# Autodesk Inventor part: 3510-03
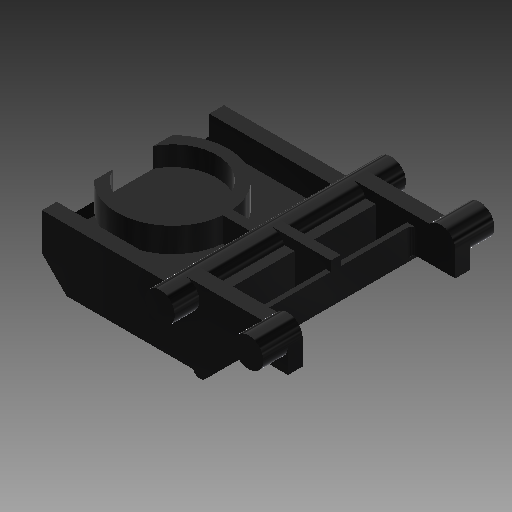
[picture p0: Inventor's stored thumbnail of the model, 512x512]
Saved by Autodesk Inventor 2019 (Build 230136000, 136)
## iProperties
Company: Autodesk Inc.
Created: 2008-12
Part Number: 3510-03
Document SubType Name: Modeling
Designer: Autodesk Inc.
Density: 0.899 g/cm^3
Material: Polypropylene
Mass: 1.31091 g
Surface Area: 20.6383 cm^2
Volume: 1.45818 cm^3
Appearance: Smooth - Black
Description: CARTRIDGE RETAINER
Author: Inventor
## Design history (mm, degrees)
sketch "Sketch1"
  geometry: L1 (-23.967, -12.692)-(-23.967, -6.392); L2 (-3.367, -8.392)-(-3.367, -8.953); L3 (-9.467, -4.892)-(-1.585, -4.892); L4 (1.033, -5.892)-(1.033, -8.392); L5 (-7.387, -12.972)-(-3.367, -8.953); L6 (-23.967, -6.392)-(-10.967, -6.392); L7 (1.033, -8.392)-(-3.367, -8.392); L8 (-8.624, -12.692)-(-23.967, -12.692); A1 r 0.75 centre (-7.917, -12.442) between (-8.624, -12.692) and (-7.387, -12.972); A2 r 1.5 centre (-0.467, -5.892) between (1.033, -5.892) and (-1.585, -4.892); A3 r 1.5 centre (-9.467, -6.392) between (-9.467, -4.892) and (-10.967, -6.392)
  constraints: 16 end point, 6 point on circle, 4 parallel, 3 centre point, 3 tangent, 2 horizontal, 1 equal radius, 1 perpendicular
  dimensions: "d32" = 1.5 radius of A2; "d33" = 0.75 radius of A1; "d34" = 45 deg angle of L4 L5; "d37" = 3.5 distance between parallel lines of L7 L3; "d38" = 4.3 distance between parallel lines of L7 L8; "d39" = 2 distance between parallel lines of L7 L6; "d40" = 2.5 distance from line of L4.start L7; "d132" = 16.05 distance from line of A1.centre L1; "d133" = 15.34289 distance of L8.start L1.start; "d134" = 14.5 distance from line of A3.centre L1; "d135" = 20.6 distance between parallel lines of L2 L1; "d136" = 4.4 distance between parallel lines of L2 L4
extrude "Extrusion1" new body sketch "Sketch1" stored distance "d44" = 18.5; taper "d45" = 0 deg
sketch "Sketch2"
  geometry: L1 (0, 0)-(0, 18.5) reference; L2 (0, 18.5)-(-15.343, 18.5) reference; L3 (0, 17.2)-(-18.782, 17.2); L4 (-18.782, 17.2)-(-18.782, 1.3); L5 (-18.782, 1.3)-(0, 1.3); L6 (0, 1.3)-(0, 17.2); 1 further point
  constraints: 8 end point, 2 parallel, 1 horizontal, 1 perpendicular, 1 point on line
  dimensions: "d49" = 1.3 distance between parallel lines of L3 L2; "d50" = 15.9 distance of L5.end L3.start
extrude "Extrusion2" cut sketch "Sketch2" distance "d51" = 2.36; taper "d52" = 0 deg
sketch "Sketch3"
  geometry: L1 (0, 17.2)-(-15.343, 17.2) reference; L2 (0, 1.3)-(-2.5, 1.3); L3 (-2.5, 1.3)-(-2.5, 17.2); L4 (-2.5, 17.2)-(0, 17.2); L5 (0, 17.2)-(0, 1.3); 1 further point
  constraints: 8 end point, 2 parallel, 1 horizontal, 1 perpendicular, 1 point on line
  dimensions: "d53" = 2.5 distance of L3.end L4.end
extrude "Extrusion3" cut sketch "Sketch3" distance "d54" = 2; taper "d55" = 0 deg
sketch "Sketch4"
  geometry: C1 r 1.5 at (-0.467, -5.892); C2 r 1.5 at (-9.467, -6.392); A1 r 1.5 centre (-0.467, -5.892) between (1.033, -5.892) and (-1.585, -4.892) reference; A2 r 1.5 centre (-9.467, -6.392) between (-9.467, -4.892) and (-10.967, -6.392) reference
  constraints: 2 centre point, 2 coincident, 1 concentric
  dimensions: "d56" = 3 diameter of C2
extrude "Extrusion4" join sketch "Sketch4" distance "d57" = 2.5; taper "d58" = 0 deg
sketch "Sketch5"
  geometry: C1 r 1.5 at (9.467, -6.392); C2 r 1.5 at (0.467, -5.892); A1 r 1.5 centre (9.467, -6.392) between (10.967, -6.392) and (9.467, -4.892) reference; A2 r 1.5 centre (0.467, -5.892) between (1.585, -4.892) and (-1.033, -5.892) reference
  constraints: 2 centre point, 2 coincident, 2 concentric
extrude "Extrusion5" join sketch "Sketch5" distance "d59" = 2.5; taper "d60" = 0 deg
sketch "Sketch6"
  geometry: L1 (0, -18.5)-(0, 0) reference; L2 (0, -18.5)-(4.4, -18.5) reference; L3 (0, -17)-(5.955, -17); L4 (5.955, -17)-(5.955, -1.5); L5 (5.955, -1.5)-(0, -1.5); L6 (0, -1.5)-(0, -17)
  constraints: 8 end point, 2 parallel, 1 horizontal, 1 perpendicular, 1 point on line
  dimensions: "d61" = 1.5 distance between parallel lines of L2 L3; "d62" = 15.5 distance of L3.end L4.end
extrude "Extrusion6" cut sketch "Sketch6" extent not by distance; stored distance "d63" = 2.5; taper "d64" = 0 deg
fillet "Fillet1" dims "d65" = 0.5
fillet "Fillet2" dims "d66" = 0.25
sketch "Sketch7"
  geometry: L1 (0, 0)-(13, 0) reference; L2 (0, 0)-(0, 18.5) reference; L3 (0, 1.5)-(11.5, 1.5); L4 (11.5, 1.5)-(11.5, 17); L5 (11.5, 17)-(0, 17); L6 (0, 17)-(0, 1.5)
  constraints: 8 end point, 2 parallel, 1 horizontal, 1 perpendicular, 1 point on line
  dimensions: "d67" = 1.5 distance between parallel lines of L1 L3; "d68" = 15.5 distance of L3.end L4.end; "d71" = 11.5 distance of L3.start L3.end
extrude "Extrusion7" cut sketch "Sketch7" distance "d69" = 2.5; taper "d70" = 0 deg
chamfer "Chamfer2" distance "d72" = 1; stored, may be unused: second distance "d73" = 2, angle "d74" = 45 deg
sketch "Sketch8"
  geometry: L1 (0, 1.5)-(0, 17) reference; L2 (0, 1.5)-(11.5, 1.5) reference; A1 r 5.65 centre (4, 9.25) between (0, 5.26) and (0, 13.24)
  constraints: 2 point on circle, 2 point on line, 1 centre point
  dimensions: "d75" = 11.3 diameter of A1; "d76" = 4 distance from line of L1 A1.centre; "d77" = 7.75 distance from line of L2 A1.centre
extrude "Extrusion8" join sketch "Sketch8" stored distance "d78" = 2.5; taper "d79" = 0 deg
sketch "Sketch9"
  geometry: C1 r 4.5 at (0, 0); A1 r 5.65 centre (0, 0) between (-4, -3.99) and (-4, 3.99) reference
  constraints: 1 centre point, 1 coincident
  dimensions: "d80" = 9 diameter of C1
extrude "Extrusion9" cut sketch "Sketch9" distance "d81" = 2; taper "d82" = 0 deg
sketch "Sketch10"
  geometry: L1 (11.5, 0)-(0, 0) reference; L2 (12.5, 2.5)-(11.5, 1.5) reference; L3 (0, 0)-(0, 2.5) reference; L4 (0, 0.5)-(0.5, 0)
  constraints: 2 end point, 2 point on line, 1 perpendicular
  dimensions: "d83" = 0.5 distance from line of L1 L4.start
extrude "Extrusion10" join sketch "Sketch10" stored distance "d84" = 2; taper "d85" = 0 deg
sketch "Sketch11"
  geometry: L1 (11.5, 2.5)-(11.5, 0) reference; L2 (11.5, 0)-(0, 0) reference; L3 (11.5, 0.636)-(10.864, 0)
  constraints: 2 end point, 2 point on line
  dimensions: "d86" = 0.63568 distance from line of L2 L3.start; "d87" = 45 deg angle of L2 L3
extrude "Extrusion11" join sketch "Sketch11" stored distance "d88" = 2; taper "d89" = 0 deg
sketch "Sketch12"
  geometry: L1 (12.5, 1.5)-(0, 1.5) reference; L2 (13, 18.5)-(13, 0) reference; L3 (13, 18.5)-(0, 18.5) reference; L4 (0, 17)-(12.5, 17) reference; L5 (12.5, 1.5)-(12.5, 17) reference; L6 (9.65, 9.25)-(12.67, 9.25); L7 (7, 1.5)-(7, 4.462); L8 (7, 14.038)-(7, 17); A1 r 5.65 centre (4, 9.25) between (0, 5.26) and (0, 13.24) reference
  constraints: 6 end point, 3 perpendicular, 3 point on circle, 2 point on line
  dimensions: "d92" = 9.25 distance between parallel lines of L3 L6 (derived); "d93" = 6 distance between parallel lines of L2 L8; "d94" = 6 distance between parallel lines of L2 L7; "d95" = 0.33034 distance from line of L6.end L2
feature "Rib1" sketch "Sketch12" dims "d97" = 1, "d98" = 0, "Rib_Thickness" = 1
sketch "Sketch14"
  geometry: L1 (0, 0)-(0, -18.5) reference; L2 (6.6, -17)-(0, -17); L3 (0, -17)-(0, -1.5); L4 (0, -1.5)-(6.6, -1.5); L5 (6.6, -1.5)-(6.6, -17)
  constraints: 8 end point, 2 parallel, 1 horizontal, 1 perpendicular, 1 point on line
extrude "Extrusion12" cut sketch "Sketch14" distance "d99" = 1; taper "d100" = 0 deg
sketch "Sketch15"
  geometry: C1 r 1.5 at (9.467, -6.392); A1 r 1.5 centre (9.467, -6.392) between (9.467, -4.892) and (10.967, -6.392) reference
  constraints: 1 centre point, 1 coincident, 1 concentric
extrude "Extrusion13" join sketch "Sketch15" stored distance "d101" = 1; taper "d102" = 0 deg
sketch "Sketch16"
  geometry: L1 (-23.967, -8.392)-(-15.467, -8.392) reference; L2 (-15.467, -8.392)-(-15.467, -6.392) reference; L3 (-15.467, -6.392)-(-10.967, -6.392) reference; L4 (-8.053, -5.892)-(-3.367, -5.892) reference; L5 (-3.367, -5.892)-(-3.367, -8.953) reference; L6 (-3.367, -8.953)-(-7.387, -12.972) reference; L7 (-8.624, -12.692)-(-8.624, -8.332) reference; L8 (-8.624, -8.332)-(-11.124, -8.332) reference; L9 (-11.124, -8.332)-(-11.124, -10.332) reference; L10 (-11.124, -10.332)-(-23.967, -10.332) reference; L11 (-23.967, -10.332)-(-23.967, -8.392) reference; L12 (-7.053, -11.224)-(-7.053, -5.892); L13 (-4.867, -9.039)-(-4.867, -5.892); L14 (-4.867, -9.039)-(-7.053, -11.224); L15 (-4.867, -5.892)-(-7.053, -5.892); A1 r 1.5 centre (-9.467, -6.392) between (-8.053, -5.892) and (-10.967, -6.392) reference; A2 r 0.75 centre (-7.917, -12.442) between (-8.624, -12.692) and (-7.387, -12.972) reference
  constraints: 8 end point, 3 parallel, 2 point on line, 1 collinear
  dimensions: "d103" = 1 distance between parallel lines of L6 L14; "d104" = 1.5 distance between parallel lines of L5 L13; "d105" = 1 distance from line of L4.start L12
extrude "Extrusion14" cut sketch "Sketch16" stored distance "d106" = 15.5; taper "d107" = 0 deg
fillet "Fillet3" dims "d108" = 0.5
chamfer "Chamfer3" distance "d109" = 1; stored, may be unused: second distance "d110" = 2, angle "d111" = 45 deg
sketch "Sketch17"
  geometry: L1 (0, 1.5)-(0, 0) reference; L2 (6.1, 16.5)-(6.1, 2) reference; L3 (-1.657, 1.3)-(-1.657, 17.2) reference; L4 (6.1, 9.25)-(0, 9.25)
  constraints: 2 end point, 1 midpoint, 1 point on line
feature "Rib2" sketch "Sketch17" dims "d112" = 1 (= Rib_Thickness), "d113" = 1, "d114" = 0
sketch "Sketch20"
  geometry: L1 (0, -1.3)-(15.343, -1.3) reference; L2 (0, -1.3)-(0, 0) reference; L3 (6.3, -1.3)-(6.3, -17.758)
  constraints: 2 end point, 1 parallel, 1 point on line
  dimensions: "d122" = 6.3 distance between parallel lines of L2 L3
feature "Rib5" sketch "Sketch20" dims "d123" = 1 (= Rib_Thickness), "d124" = 1, "d125" = 0
sketch "Sketch21"
  geometry: L1 (0, 1.3)-(0, 17.2) reference; L2 (0, 9.25)-(16.061, 9.25)
  constraints: 2 end point, 1 midpoint, 1 perpendicular
feature "Rib6" sketch "Sketch21" dims "d126" = 1 (= Rib_Thickness), "d127" = 1, "d128" = 0
chamfer "Chamfer4" distance "d129" = 2.5; stored, may be unused: second distance "d130" = 2, angle "d131" = 45 deg
body "Solid1"
node "Project Cut Edges1"
other parameters: "d8" = 1.5, "d12" = 45 deg, "d22" = 3.5, "d90" = 7
